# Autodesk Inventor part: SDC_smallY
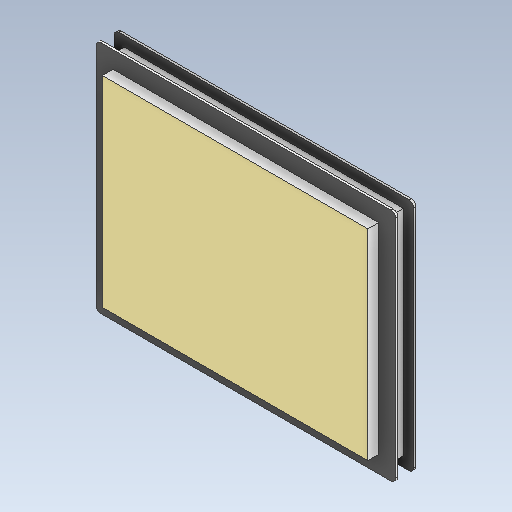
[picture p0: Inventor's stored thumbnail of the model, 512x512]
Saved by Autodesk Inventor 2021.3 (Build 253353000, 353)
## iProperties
Created: 2022-01
Part Number: SDC_smallY
Material: アルミニウム 6061
Document SubType Name: Modeling
Designer: kengo
Density: 2.7 g/cm^3
Appearance: アルミニウム - フラット
Mass: 570752 g
Surface Area: 39800 cm^2
Volume: 211390 cm^3
Author: kengo
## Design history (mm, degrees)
sketch "スケッチ1"
  geometry: L1 (-665, 370.141)-(665, 370.141); L2 (665, 370.141)-(665, -671.859); L3 (665, -671.859)-(-665, -671.859); L4 (-665, -671.859)-(-665, 370.141); 1 further point
  constraints: 8 end point, 2 parallel, 1 horizontal, 1 perpendicular
  dimensions: "d0" = 1330 distance of L1.start L1.end; "d1" = 1042 distance of L1.end L2.end
extrude "押し出し1" new body sketch "スケッチ1" distance "d2" = 10; taper "d3" = 0 deg
sketch "スケッチ2"
  geometry: L1 (-620, 325.141)-(620, 325.141); L2 (620, 325.141)-(620, -626.859); L3 (620, -626.859)-(-620, -626.859); L4 (-620, -626.859)-(-620, 325.141); L5 (665, 370.141)-(-665, 370.141) reference; L6 (-665, 370.141)-(-665, -671.859) reference; L7 (665, -671.859)-(665, 370.141) reference; L8 (-665, -671.859)-(665, -671.859) reference; 1 further point
  constraints: 8 end point, 2 parallel, 1 horizontal, 1 perpendicular
  dimensions: "d4" = 45 distance between parallel lines of L5 L1; "d5" = 45 distance between parallel lines of L6 L4; "d6" = 45 distance between parallel lines of L7 L2; "d7" = 45 distance between parallel lines of L8 L3
extrude "押し出し2" join sketch "スケッチ2" distance "d8" = 70; taper "d9" = 0 deg
sketch "スケッチ3"
  geometry: L1 (-665, 370.141)-(665, 370.141); L2 (665, 370.141)-(665, -671.859); L3 (665, -671.859)-(-665, -671.859); L4 (-665, -671.859)-(-665, 370.141); 1 further point
  constraints: 8 end point, 2 parallel, 1 horizontal, 1 perpendicular
extrude "押し出し3" join sketch "スケッチ3" distance "d10" = 10; taper "d11" = 0 deg
sketch "スケッチ4"
  geometry: L1 (-590, 295.141)-(590, 295.141); L2 (590, 295.141)-(590, -596.859); L3 (590, -596.859)-(-590, -596.859); L4 (-590, -596.859)-(-590, 295.141); L5 (665, 370.141)-(-665, 370.141) reference; L6 (665, -671.859)-(665, 370.141) reference; L7 (-665, 370.141)-(-665, -671.859) reference; L8 (-665, -671.859)-(665, -671.859) reference; 1 further point
  constraints: 8 end point, 2 parallel, 1 horizontal, 1 perpendicular
  dimensions: "d13" = 75 distance between parallel lines of L5 L1; "d14" = 75 distance between parallel lines of L6 L2; "d15" = 75 distance between parallel lines of L7 L4; "d16" = 75 distance between parallel lines of L8 L3
extrude "押し出し4" join sketch "スケッチ4" distance "d17" = 48; taper "d19" = 0 deg; dims "d18" = 138, "d20" = 0
fillet "フィレット1" dims "d21" = 20
node "ソリッド1"
